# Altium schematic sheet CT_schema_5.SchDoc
size 302 x 256 mm
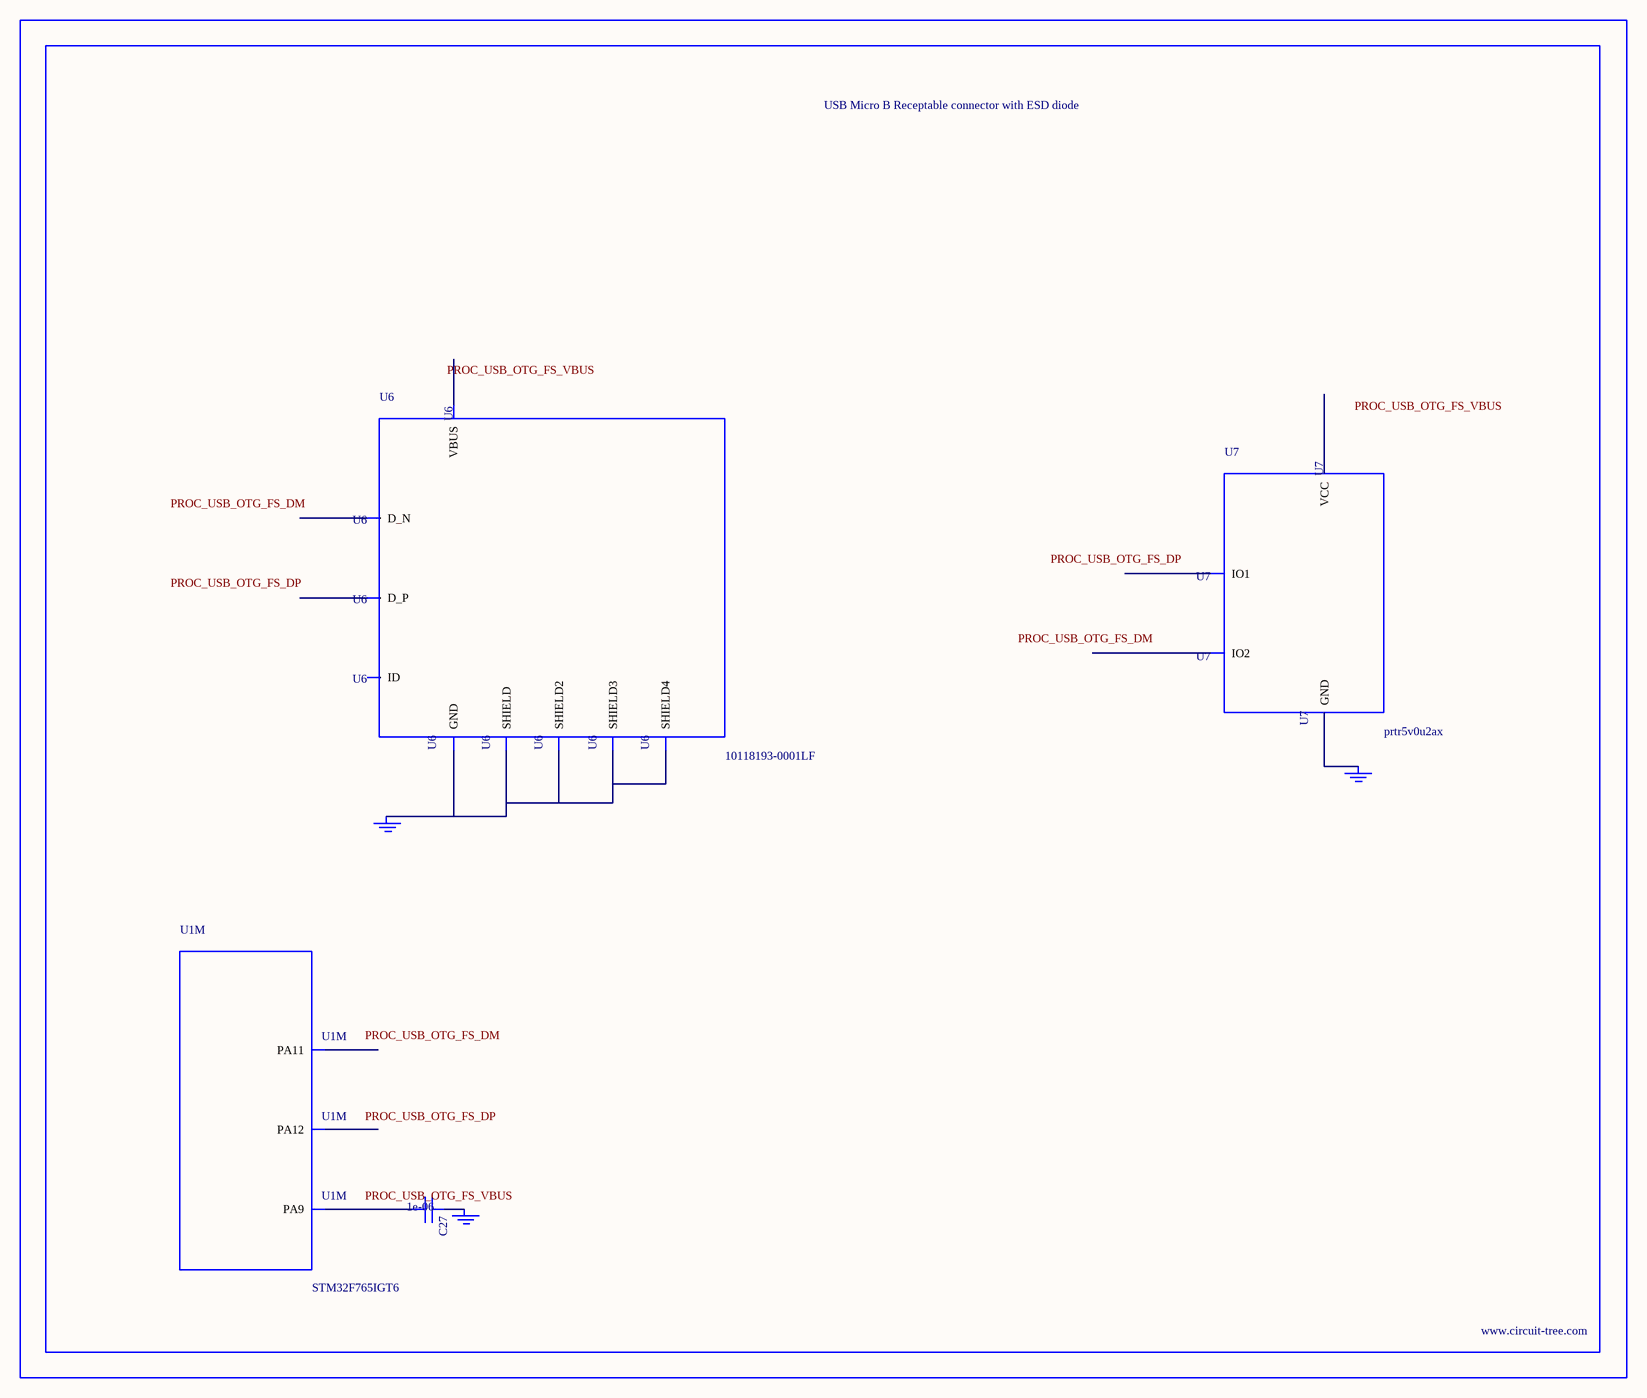
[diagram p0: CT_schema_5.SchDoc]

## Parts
BORDER4  (no value)
C27  1e-06  [C0603]
GND_INSTANCE_4_0  (no value)
GND_INSTANCE_4_1  (no value)
GND_INSTANCE_4_2  (no value)
U1  STM32F765IGT6  [LQFP176]  (part M of 14)
U6  10118193-0001LF  [FCI_10118193-0001LF]
U7  prtr5v0u2ax  [SOT143B]

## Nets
NetC27_1: C27.1 GND_INSTANCE_4_1.0(GND)
NetC27_2: C27.2 U1.120(PA9)
NetGND_INSTANCE_4_0_0: GND_INSTANCE_4_0.0(GND) U6.5(GND) U6.6(SHIELD) U6.7(SHIELD2) U6.8(SHIELD3) U6.9(SHIELD4)
NetGND_INSTANCE_4_2_0: GND_INSTANCE_4_2.0(GND) U7.1(GND)

Not connected (* = marked no-connect by the designer): U1 122(PA11) 123(PA12); U6 1(VBUS) 2(D_N) 3(D_P) 4(ID); U7 2(IO1) 3(IO2) 4(VCC)

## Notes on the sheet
- Labels drawn without touching a wire or pin: PROC_USB_OTG_FS_DM, PROC_USB_OTG_FS_DP, PROC_USB_OTG_FS_VBUS

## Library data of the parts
BORDER4 = BORDER_PAGE4
C27 = C0603C105K3RACTU
GND_INSTANCE_4_0-GND_INSTANCE_4_2 = GND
